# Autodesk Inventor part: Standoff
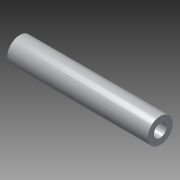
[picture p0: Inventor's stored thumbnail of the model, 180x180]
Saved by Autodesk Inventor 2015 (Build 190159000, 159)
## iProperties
Created: 2014-07
Part Number: Standoff
Material: Aluminum 6061
Document SubType Name: Modeling
Designer: Admin
Density: 2.71 g/cm^3
Appearance: Aluminum - Flat
Author: Admin
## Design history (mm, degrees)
sketch "Sketch1"
  geometry: C1 r 3.175 at (0, 0); C2 r 6.223 at (0, 0); 1 further point
  constraints: 2 centre point, 2 coincident
  dimensions: "d0" = 6.35 diameter of C1; "d1" = 12.446 diameter of C2
extrude "Extrusion1" new body sketch "Sketch1" distance "d2" = 69.85; taper "d3" = 0 deg
body "Solid1"
